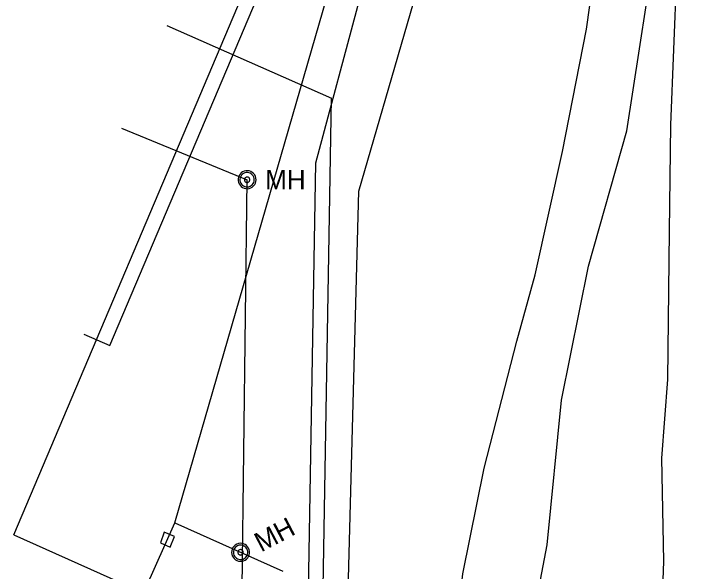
# Model space of a CAD drawing. Extents: x 596028 to 606371, y 330010 to 403088.
# Drawn here: x 604662.9 to 604897.2, y 332850.6 to 333039.5 of the extents above; entities that cross this region are included whole.
import ezdxf

# ---------------------------------------------------------------- set-up
doc = ezdxf.new("R2010")
doc.units = 0
for name, color, linetype in [('E_FTMS_Conduit', 7, 'Continuous'), ('E_LTG_CID', 7, 'Continuous'), ('E_UTL_E_UG', 7, 'Continuous'), ('E_UTL_G_UG', 7, 'Continuous'), ('E_UTL_SAN_MH', 7, 'Continuous'), ('E_UTL_SAN_UG', 7, 'Continuous'), ('E_UTL_W_MH', 7, 'Continuous'), ('E_UTL_W_UG', 7, 'Continuous')]:
    doc.layers.add(name, color=color, linetype=linetype)

msp = doc.modelspace()

# ---------------------------------------------------------------- linework, layer by layer
at = {"layer": 'E_FTMS_Conduit'}
msp.add_lwpolyline([(604833.62, 332786.94), (604837.8, 332828.79), (604843.62, 332859.54), (604848.45, 332908.55), (604857.59, 332953.99), (604870.57, 332999.81), (604881.56, 333070.85), (604883.3, 333104.02), (604886.34, 333150.08), (604892.01, 333248.16), (604893.18, 333291.76), (604894.37, 333357.39), (604896.64, 333466.11), (604897.17, 333555.99)], dxfattribs=at)
at = {"layer": 'E_LTG_CID'}
msp.add_lwpolyline([(604879.6, 332255.02), (604881.21, 332520.43), (604882.73, 332780.27), (604878.2, 332790.52), (604877.91, 332791.78), (604881.34, 332802.26), (604883.13, 332854.03), (604882.52, 332888.97), (604884.51, 332915.54), (604885.08, 332965.87), (604885.55, 333001.94), (604887.55, 333053.11)], dxfattribs=at)
at = {"layer": 'E_UTL_E_UG'}
msp.add_lwpolyline([(604808.26, 332737.58), (604807.78, 332750.65), (604807.96, 332775.5), (604808.38, 332791.31), (604815.08, 332849.74), (604822.32, 332885.57), (604833.34, 332928.58), (604839.6, 332951.01), (604848.87, 332992.8), (604856.97, 333034.28), (604864.88, 333090.5), (604871.07, 333164.58), (604871.07, 333164.57), (604871.34, 333168.95), (604872.08, 333173.54), (604873.02, 333206.22), (604875.47, 333283.07), (604876.52, 333351.85), (604877.02, 333463.99), (604875.73, 333577.42)], dxfattribs=at)
at = {"layer": 'E_UTL_G_UG'}
msp.add_lwpolyline([(604773.9, 332759.22), (604779.8, 332979.43), (604806.41, 333071.33), (604840.32, 333103.89)], dxfattribs=at)
at = {"layer": 'E_UTL_SAN_MH'}
for points in [[(604744.97, 332983.28), (604744.92, 332983.86), (604744.75, 332984.42), (604744.49, 332984.93), (604744.13, 332985.39), (604743.69, 332985.77), (604743.19, 332986.06), (604742.64, 332986.25), (604742.06, 332986.33), (604741.48, 332986.31), (604740.92, 332986.17), (604740.39, 332985.93), (604739.92, 332985.59), (604739.52, 332985.17), (604739.2, 332984.68), (604738.99, 332984.14), (604738.88, 332983.57), (604738.88, 332982.99), (604738.99, 332982.42), (604739.2, 332981.88), (604739.52, 332981.39), (604739.92, 332980.97), (604740.39, 332980.64), (604740.92, 332980.4), (604741.48, 332980.26), (604742.06, 332980.23), (604742.64, 332980.31), (604743.19, 332980.5), (604743.69, 332980.79), (604744.13, 332981.17), (604744.49, 332981.63), (604744.75, 332982.15), (604744.92, 332982.7), (604744.97, 332983.28)], [(604744.36, 332983.28), (604744.32, 332983.75), (604744.19, 332984.19), (604743.97, 332984.6), (604743.69, 332984.97), (604743.34, 332985.27), (604742.93, 332985.51), (604742.49, 332985.66), (604742.03, 332985.72), (604741.57, 332985.7), (604741.12, 332985.59), (604740.7, 332985.4), (604740.32, 332985.13), (604740, 332984.79), (604739.75, 332984.4), (604739.57, 332983.97), (604739.48, 332983.52), (604739.48, 332983.05), (604739.57, 332982.59), (604739.75, 332982.16), (604740, 332981.77), (604740.32, 332981.44), (604740.7, 332981.17), (604741.12, 332980.97), (604741.57, 332980.86), (604742.03, 332980.84), (604742.49, 332980.91), (604742.93, 332981.06), (604743.34, 332981.29), (604743.69, 332981.6), (604743.97, 332981.96), (604744.19, 332982.37), (604744.32, 332982.82), (604744.36, 332983.28)], [(604742.83, 332983.28), (604742.82, 332983.46), (604742.77, 332983.62), (604742.69, 332983.78), (604742.58, 332983.92), (604742.45, 332984.03), (604742.3, 332984.12), (604742.13, 332984.17), (604741.96, 332984.2), (604741.79, 332984.19), (604741.62, 332984.15), (604741.46, 332984.08), (604741.32, 332983.98), (604741.2, 332983.85), (604741.1, 332983.7), (604741.04, 332983.54), (604741.01, 332983.37), (604741.01, 332983.2), (604741.04, 332983.02), (604741.1, 332982.86), (604741.2, 332982.72), (604741.32, 332982.59), (604741.46, 332982.49), (604741.62, 332982.42), (604741.79, 332982.38), (604741.96, 332982.37), (604742.13, 332982.39), (604742.3, 332982.45), (604742.45, 332982.54), (604742.58, 332982.65), (604742.69, 332982.79), (604742.77, 332982.94), (604742.82, 332983.11), (604742.83, 332983.28)]]:
    msp.add_lwpolyline(points, dxfattribs=at)
at = {"layer": 'E_UTL_SAN_UG'}
for p, q in [((604765.2, 332988.96), (604794.38, 333097.76)), ((604699.37, 333000.76), (604741.92, 332983.28)), ((604738.77, 332715.93), (604741.92, 332983.28))]:
    msp.add_line(p, q, dxfattribs=at)
msp.add_lwpolyline([(604771.15, 332776.81), (604761.61, 332777.87), (604765.2, 332988.96)], dxfattribs=at)
at = {"layer": 'E_UTL_W_MH'}
msp.add_lwpolyline([(604715.9, 332858.75), (604717.35, 332862.37), (604713.83, 332863.88), (604712.53, 332860.26)], close=True, dxfattribs=at)
for points in [[(604742.41, 332858.46), (604742.1, 332858.95), (604741.69, 332859.36), (604741.22, 332859.7), (604740.69, 332859.93), (604740.12, 332860.07), (604739.54, 332860.09), (604738.96, 332860), (604738.42, 332859.81), (604737.92, 332859.51), (604737.48, 332859.13), (604737.13, 332858.67), (604736.86, 332858.15), (604736.7, 332857.59), (604736.65, 332857.01), (604736.71, 332856.44), (604736.88, 332855.88), (604737.15, 332855.37), (604737.52, 332854.91), (604737.96, 332854.54), (604738.46, 332854.25), (604739.01, 332854.06), (604739.59, 332853.99), (604740.17, 332854.02), (604740.73, 332854.16), (604741.26, 332854.41), (604741.73, 332854.75), (604742.13, 332855.17), (604742.44, 332855.66), (604742.65, 332856.2), (604742.75, 332856.77), (604742.75, 332857.35), (604742.63, 332857.92), (604742.41, 332858.46)], [(604741.87, 332858.18), (604741.62, 332858.57), (604741.3, 332858.9), (604740.91, 332859.17), (604740.49, 332859.36), (604740.04, 332859.46), (604739.57, 332859.48), (604739.11, 332859.41), (604738.68, 332859.25), (604738.28, 332859.02), (604737.93, 332858.71), (604737.64, 332858.34), (604737.43, 332857.93), (604737.31, 332857.48), (604737.27, 332857.02), (604737.31, 332856.56), (604737.45, 332856.11), (604737.66, 332855.7), (604737.95, 332855.34), (604738.31, 332855.04), (604738.71, 332854.81), (604739.15, 332854.66), (604739.61, 332854.6), (604740.08, 332854.62), (604740.53, 332854.74), (604740.95, 332854.93), (604741.33, 332855.2), (604741.64, 332855.54), (604741.89, 332855.94), (604742.06, 332856.37), (604742.14, 332856.83), (604742.14, 332857.29), (604742.05, 332857.75), (604741.87, 332858.18)], [(604740.52, 332857.47), (604740.43, 332857.61), (604740.3, 332857.74), (604740.16, 332857.84), (604740, 332857.91), (604739.83, 332857.95), (604739.66, 332857.95), (604739.49, 332857.93), (604739.32, 332857.87), (604739.17, 332857.78), (604739.04, 332857.67), (604738.93, 332857.53), (604738.86, 332857.37), (604738.81, 332857.21), (604738.79, 332857.03), (604738.81, 332856.86), (604738.86, 332856.69), (604738.94, 332856.54), (604739.05, 332856.4), (604739.18, 332856.29), (604739.34, 332856.2), (604739.5, 332856.15), (604739.67, 332856.12), (604739.85, 332856.13), (604740.02, 332856.18), (604740.17, 332856.25), (604740.32, 332856.35), (604740.43, 332856.48), (604740.53, 332856.63), (604740.59, 332856.79), (604740.62, 332856.96), (604740.62, 332857.13), (604740.59, 332857.3), (604740.52, 332857.47)]]:
    msp.add_lwpolyline(points, dxfattribs=at)
at = {"layer": 'E_UTL_W_UG'}
for p, q in [((604717.45, 332867), (604828.69, 333252.06)), ((604662.86, 332863.01), (604745.33, 333057.64)), ((604714.7, 333035.54), (604770.58, 333010.92)), ((604766.98, 332799.55), (604770.58, 333010.92)), ((604699.5, 332826.87), (604717.45, 332867)), ((604717.45, 332867), (604753.99, 332850.65)), ((604662.86, 332863.01), (604754.6, 332821.96))]:
    msp.add_line(p, q, dxfattribs=at)
msp.add_lwpolyline([(604686.56, 332931.01), (604695.45, 332927.09), (604802.4, 333179.5)], dxfattribs=at)

# ---------------------------------------------------------------- texts
at = {"layer": 'E_UTL_SAN_MH'}
msp.add_text('MH', height=6.6, dxfattribs=at).set_placement((604748.03, 332979.98))
at = {"layer": 'E_UTL_W_MH'}
msp.add_text('MH', height=6.6, rotation=27.7427, dxfattribs=at).set_placement((604746.65, 332856.96))

doc.saveas('drawing.dxf')
